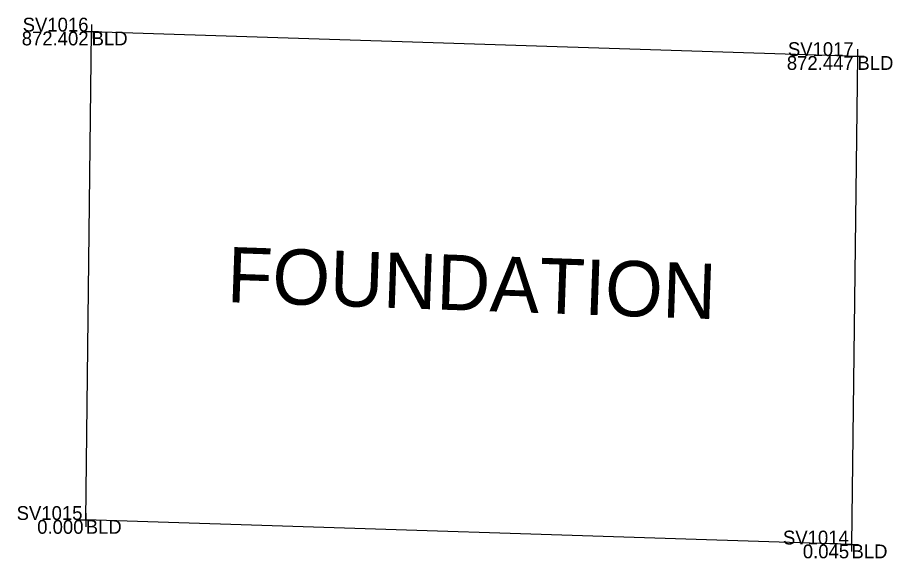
# Model space of a CAD drawing. Extents: x 2005176 to 2005823, y 572472 to 572942.
# Drawn here: x 2005302.4 to 2005365.7, y 572902.4 to 572941.5 of the extents above; entities that cross this region are included whole.
import ezdxf

# ---------------------------------------------------------------- set-up
doc = ezdxf.new("R2010")
doc.units = 0
for name, color, linetype in [('BD_X_Building', 7, 'Continuous'), ('BD_X_Text', 7, 'Continuous'), ('DV_X_Property_Line', 7, 'Continuous'), ('SV_P_Mon_Cells_Set', 7, 'Continuous'), ('SV_X_Control_Cells_Found', 7, 'Continuous'), ('SV_X_Mon_Cells_Found', 7, 'Continuous')]:
    doc.layers.add(name, color=color, linetype=linetype)

msp = doc.modelspace()

# ---------------------------------------------------------------- linework, layer by layer
at = {"layer": 'BD_X_Building'}
msp.add_lwpolyline([(2005362.695, 572903.429), (2005307.319, 572905.202), (2005307.747, 572940.527), (2005363.123, 572938.754)], close=True, dxfattribs=at)
at = {"layer": 'SV_P_Mon_Cells_Set'}
for p, q in [((2005307.747, 572941.027), (2005307.747, 572940.027)), ((2005307.247, 572940.527), (2005308.247, 572940.527)), ((2005307.747, 572940.527), (2005307.747, 572940.527)), ((2005362.623, 572938.754), (2005363.623, 572938.754)), ((2005363.123, 572939.254), (2005363.123, 572938.254)), ((2005363.123, 572938.754), (2005363.123, 572938.754)), ((2005306.819, 572905.202), (2005307.819, 572905.202)), ((2005307.319, 572905.702), (2005307.319, 572904.702)), ((2005307.319, 572905.202), (2005307.319, 572905.202)), ((2005362.695, 572903.929), (2005362.695, 572902.929)), ((2005362.195, 572903.429), (2005363.195, 572903.429)), ((2005362.695, 572903.429), (2005362.695, 572903.429))]:
    msp.add_line(p, q, dxfattribs=at)

# ---------------------------------------------------------------- texts
at = {"layer": 'BD_X_Text'}
msp.add_text('FOUNDATION', height=4, rotation=358, dxfattribs=at).set_placement((2005317.498, 572920.957))
at = {"layer": 'DV_X_Property_Line'}
for p in [(2005307.747, 572939.527), (2005363.123, 572937.754), (2005307.319, 572904.202), (2005362.695, 572902.429)]:
    msp.add_text('BLD', height=1, dxfattribs=at).set_placement(p)
at = {"layer": 'SV_X_Control_Cells_Found'}
for s, p in [('SV1016', (2005302.76, 572940.527)), ('SV1017', (2005358.097, 572938.754)), ('SV1015', (2005302.325, 572905.202)), ('SV1014', (2005357.741, 572903.429))]:
    msp.add_text(s, height=1, dxfattribs=at).set_placement(p)
at = {"layer": 'SV_X_Mon_Cells_Found'}
for s, p in [('872.402', (2005302.691, 572939.527)), ('872.447', (2005358.02, 572937.754)), ('0.000', (2005303.812, 572904.202)), ('0.045', (2005359.177, 572902.429))]:
    msp.add_text(s, height=1, dxfattribs=at).set_placement(p)

doc.saveas('drawing.dxf')
